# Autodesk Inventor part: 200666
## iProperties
Created: 2007-10
Part Number: 200666
Document SubType Name: Modeling
Designer: TH
Density: 7.85 g/cm^3
Mass: 30.7796 g
Surface Area: 29.6939 cm^2
Volume: 3.92097 cm^3
Material: Steel
Description: LINK PLATE
Component Category: Lower Component
Author: TH
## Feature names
1. Extrusion1
2. Hole3
3. Hole4
